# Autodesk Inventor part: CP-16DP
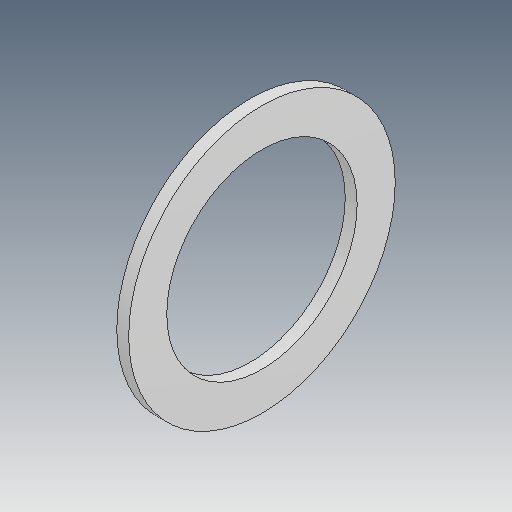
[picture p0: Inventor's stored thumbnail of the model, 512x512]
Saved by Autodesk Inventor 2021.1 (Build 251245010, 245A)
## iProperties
Created: 2021-06
Part Number: CP-16DP
Material: Ogólny
Document SubType Name: Modeling
Designer: user
Density: 1 g/cm^3
Appearance: Domyślna
Author: user
Revision Number: ÈÎºÎ
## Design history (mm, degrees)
feature "ÊäÈë1"
node "Bryła1"
